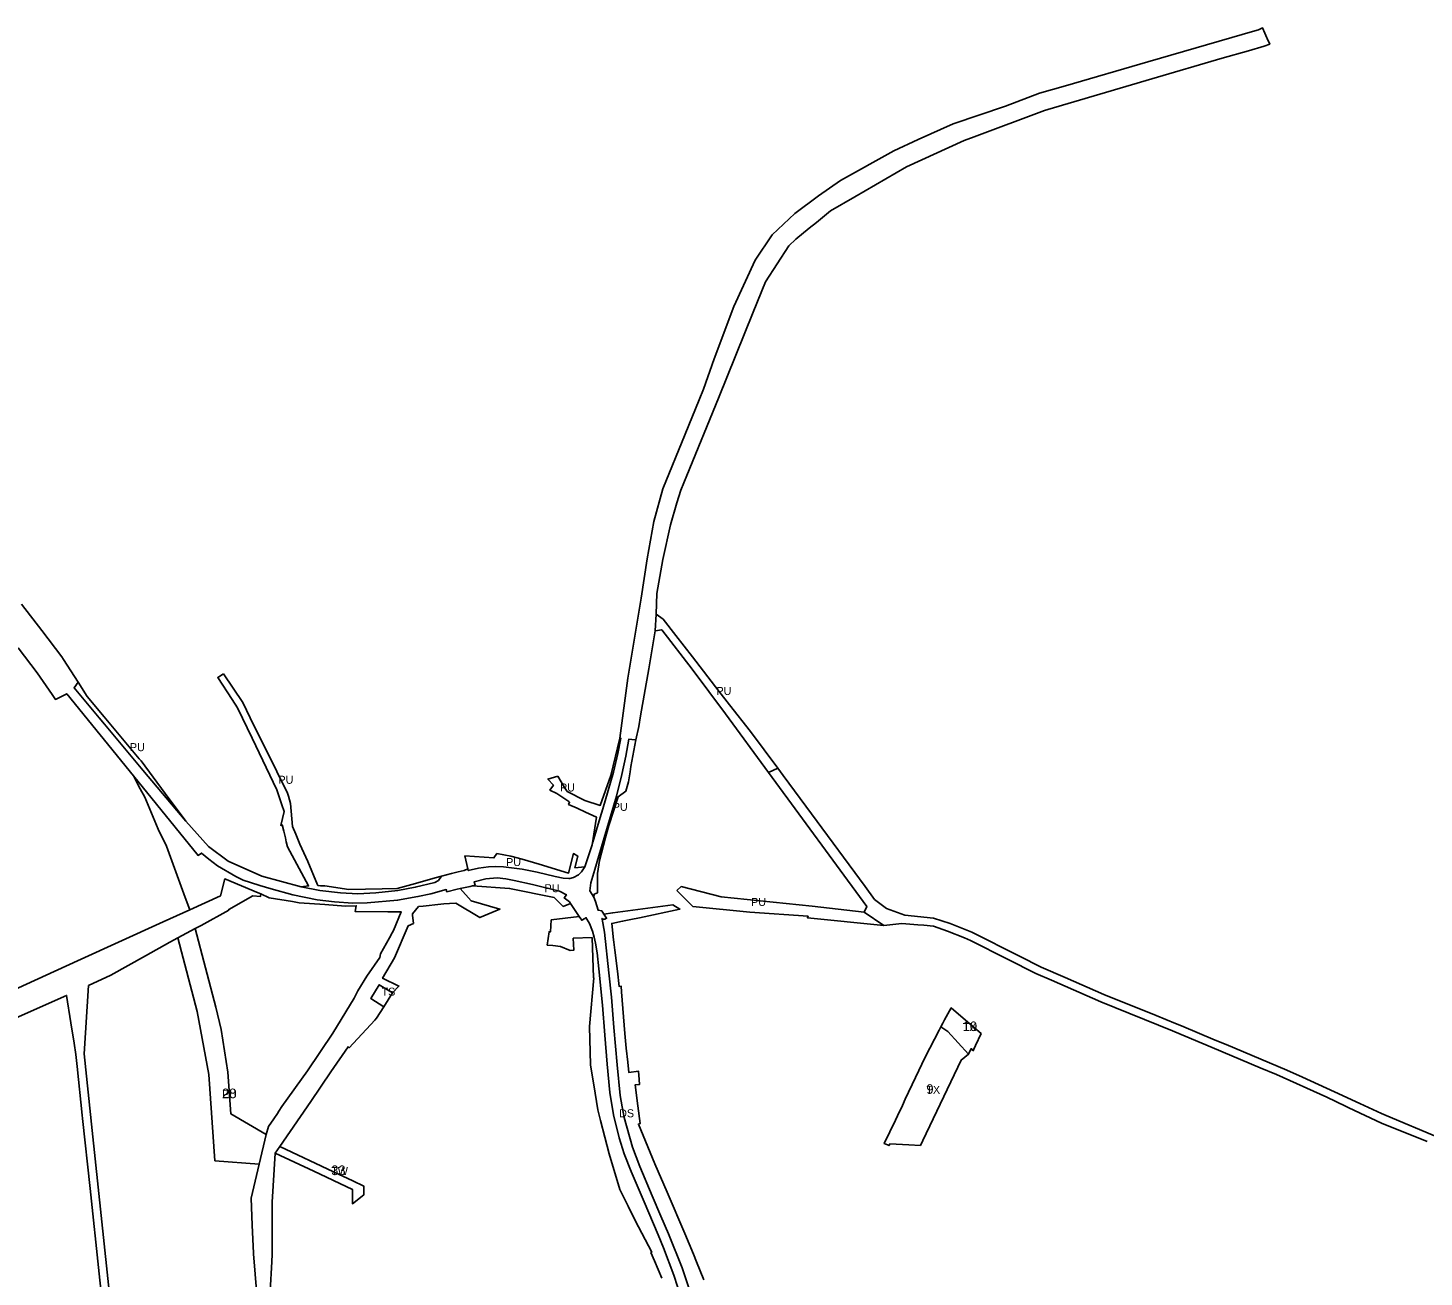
# Model space of a CAD drawing. Extents: x -521882 to -518995, y -1142400 to -1140153.
# Drawn here: x -520739 to -519867, y -1141035 to -1140255 of the extents above; entities that cross this region are included whole.
import ezdxf

# ---------------------------------------------------------------- set-up
doc = ezdxf.new("R2010")
doc.units = 0
for name, color, linetype in [('90320013', 7, 'Continuous'), ('90370013', 7, 'Continuous'), ('90390023', 7, 'Continuous'), ('90410013', 7, 'Continuous'), ('90440023', 7, 'Continuous'), ('90450013', 7, 'Continuous'), ('90450023', 7, 'Continuous'), ('ID_navrh', 7, 'Continuous')]:
    doc.layers.add(name, color=color, linetype=linetype)

msp = doc.modelspace()

# ---------------------------------------------------------------- linework, layer by layer
at = {"layer": '90320013'}
for points in [[(-520743.28, -1140615.01), (-520730.64, -1140631.58), (-520718.15, -1140647.9), (-520717.09, -1140649.55), (-520707.94, -1140663.79), (-520710.41, -1140667.24), (-520694.71, -1140686.16), (-520691.52, -1140689.98), (-520667.53, -1140718.71), (-520640.71, -1140750.61), (-520626.37, -1140766.52), (-520614.11, -1140775.58), (-520593.15, -1140785.04), (-520568.68, -1140791.66), (-520556.98, -1140793.85), (-520544.08, -1140795.45), (-520533.1, -1140795.95), (-520521.89, -1140795.42), (-520508.09, -1140793.94), (-520497.35, -1140791.93), (-520485.15, -1140788.87), (-520482.88, -1140787.7), (-520480.98, -1140785.01), (-520474.64, -1140783.36), (-520470.41, -1140782.37), (-520466.78, -1140781.53), (-520464.48, -1140780.47), (-520464.21, -1140781.48), (-520457.74, -1140780.06), (-520451.46, -1140779.1), (-520447.03, -1140778.94), (-520442.14, -1140779.17), (-520430.59, -1140780.58), (-520421.16, -1140782.56), (-520409.82, -1140785.14), (-520404.95, -1140786.22), (-520401.42, -1140786.48), (-520400.82, -1140786.35), (-520398.38, -1140785.83), (-520395.36, -1140784.1), (-520393.48, -1140782.23), (-520391.38, -1140779.15), (-520386.83, -1140765.41), (-520386.29, -1140763.79), (-520381.78, -1140748.3), (-520380.21, -1140742.93), (-520373.52, -1140720.12), (-520370.77, -1140708.37), (-520368.79, -1140698.83), (-520369.41, -1140698.76), (-520364.42, -1140661.36), (-520356.59, -1140613.91), (-520356.14, -1140611.39), (-520352.4, -1140586.73), (-520348.21, -1140563.43), (-520342.62, -1140543.01), (-520328.73, -1140508.82), (-520319.85, -1140487.51), (-520317.29, -1140480.75), (-520317.28, -1140480.73), (-520310.52, -1140461.93), (-520298.27, -1140429.16), (-520285.01, -1140400.23), (-520274.33, -1140384.38), (-520260.24, -1140370.94), (-520245.33, -1140359.99), (-520231.71, -1140350.36), (-520198.24, -1140332), (-520183.06, -1140324.86), (-520161.16, -1140315.09), (-520128.63, -1140303.97), (-520107.24, -1140295.95), (-520091.03, -1140291.29), (-520039.59, -1140276.29), (-519972.75, -1140256.9), (-519970.54, -1140256.24), (-519967.99, -1140255.12), (-519967.34, -1140256.59), (-519967.14, -1140257.04), (-519965.23, -1140261.32), (-519965.02, -1140261.78), (-519963.47, -1140265.25), (-519967, -1140266.42), (-519976.66, -1140269.42), (-519993.22, -1140274.03), (-520037.05, -1140286.83), (-520102.1, -1140306.15), (-520104.17, -1140306.68), (-520148.17, -1140323.1), (-520154.29, -1140325.48), (-520190.37, -1140341.83), (-520222.7, -1140360.61), (-520237.84, -1140369.42), (-520246.72, -1140376.59), (-520251.21, -1140380.2), (-520259.52, -1140387.05), (-520263.92, -1140391.15), (-520278.46, -1140413.78), (-520286.11, -1140432.61), (-520307.77, -1140486.46), (-520327.66, -1140534.75), (-520331.42, -1140543.88), (-520333.94, -1140551.84), (-520337.95, -1140565.45), (-520342.68, -1140587.14), (-520346.39, -1140608.35), (-520346.89, -1140621.24), (-520347.36, -1140631.75), (-520351.39, -1140655.57), (-520356.53, -1140684.75), (-520357.72, -1140691.49), (-520359.48, -1140699.91), (-520361.97, -1140699.61), (-520363.79, -1140699.4), (-520365.84, -1140710.09), (-520368.19, -1140721.56), (-520371.69, -1140734.94), (-520377.6, -1140755.34), (-520382.64, -1140772.35), (-520385.08, -1140780.78), (-520387.56, -1140789.2), (-520388.29, -1140794.2), (-520385.85, -1140798.14), (-520384.61, -1140800.83), (-520383.09, -1140806.25), (-520380.85, -1140806.63), (-520379.43, -1140808.81), (-520377.82, -1140811.29), (-520378.82, -1140811.8), (-520379.96, -1140811.88), (-520380.39, -1140811.76), (-520380.67, -1140811.43), (-520380.6, -1140811.79), (-520379.1, -1140819.91), (-520376.29, -1140845.28), (-520374.77, -1140860.47), (-520373.16, -1140879.42), (-520371.26, -1140902.9), (-520369.28, -1140921.92), (-520368.13, -1140929.14), (-520366.72, -1140935.8), (-520361.56, -1140954.25), (-520356.97, -1140966.32), (-520349.32, -1140984.59), (-520343.82, -1140997.39), (-520339.2, -1141008.34), (-520330.66, -1141029.65), (-520324.76, -1141047.17)], [(-520328.86, -1141055.37), (-520335.75, -1141034.28), (-520342.18, -1141017.11), (-520345.5, -1141009.13), (-520354.36, -1140988.48), (-520362.35, -1140969.44), (-520366.71, -1140958.45), (-520369.93, -1140948.53), (-520373.47, -1140934.03), (-520375.75, -1140920.12), (-520377.36, -1140902.45), (-520378.78, -1140884.3), (-520380.29, -1140865.65), (-520382.69, -1140842.89), (-520383.72, -1140832.94), (-520384.67, -1140826.92), (-520385.53, -1140823.04), (-520386.51, -1140819.33), (-520388.5, -1140814.63), (-520390.7, -1140810.83), (-520391.45, -1140811.33), (-520393.28, -1140812.54), (-520394.93, -1140810.08), (-520400.31, -1140802.09), (-520401.05, -1140800.99), (-520404.19, -1140798.55), (-520402.86, -1140796.64), (-520407.29, -1140794.34), (-520424.08, -1140790.09), (-520435.45, -1140787.73), (-520440.68, -1140786.74), (-520446.22, -1140786.13), (-520453.31, -1140786.74), (-520460.51, -1140788.53), (-520459.9, -1140790.65), (-520461.64, -1140791.05), (-520463.08, -1140791.37), (-520469.2, -1140792.72), (-520471.14, -1140793.15), (-520477.5, -1140794.69), (-520477.93, -1140793.38), (-520487.57, -1140796.09), (-520495.6, -1140797.79), (-520508.3, -1140799.99), (-520527.36, -1140801.68), (-520536.39, -1140801.86), (-520547.7, -1140801.1), (-520558.67, -1140799.71), (-520573.73, -1140796.75), (-520587.36, -1140792.97), (-520594.41, -1140790.88), (-520595.11, -1140790.67), (-520604.74, -1140787.54), (-520609.47, -1140785.27), (-520620.79, -1140778.52), (-520626.26, -1140774.29), (-520630.76, -1140770.61), (-520632.98, -1140772.07), (-520673.31, -1140722.41), (-520715.02, -1140671.04), (-520722.11, -1140674.56), (-520724.12, -1140671.61), (-520733.42, -1140657.97), (-520745.42, -1140642.26)]]:
    msp.add_lwpolyline(points, dxfattribs=at)
at = {"layer": '90370013'}
for points in [[(-519865.12, -1140950.76), (-519893.61, -1140939.25), (-519914.16, -1140929.63), (-519916.21, -1140928.63), (-519927.83, -1140922.94), (-519959.29, -1140908.89), (-519969.45, -1140904.62), (-519999.48, -1140892), (-520022.73, -1140882.19), (-520024.21, -1140881.57), (-520069.02, -1140863.47), (-520099.84, -1140850.03), (-520109.6, -1140845.72), (-520127.38, -1140836.75), (-520150.53, -1140825.07), (-520154.23, -1140823.56), (-520164.79, -1140819.27), (-520173.51, -1140816.17), (-520179.62, -1140815.67), (-520183.32, -1140815.4), (-520193.39, -1140814.61), (-520204.62, -1140815.75), (-520216.9, -1140807.42), (-520215.27, -1140803.99), (-520276.72, -1140720.19), (-520270.86, -1140717.61), (-520267.51, -1140722.14), (-520249.86, -1140745.99), (-520216.26, -1140791.5), (-520210.31, -1140799.64), (-520202.97, -1140805.12), (-520191.48, -1140809.25), (-520173.51, -1140811.18), (-520163.23, -1140814.61), (-520149.6, -1140820.02), (-520119.77, -1140834.99), (-520106.23, -1140841.79), (-520091.34, -1140848.28), (-520067.09, -1140858.86), (-520034.41, -1140872.06), (-520022.3, -1140876.95), (-520018.57, -1140878.52), (-519997.49, -1140887.4), (-519990.79, -1140890.22), (-519952.82, -1140906.1), (-519943.08, -1140910.55), (-519923.13, -1140919.66), (-519907.29, -1140926.89), (-519893.61, -1140933.19), (-519890.83, -1140934.46), (-519858.03, -1140948.23)], [(-520882.47, -1140917.37), (-520708.35, -1140837.86), (-520654.73, -1140813.47), (-520638.22, -1140805.93), (-520618.93, -1140797.21), (-520616.33, -1140786.69), (-520595.39, -1140795.43), (-520593.85, -1140796.07), (-520594.09, -1140797.76), (-520598.71, -1140797.27), (-520613.82, -1140805.77), (-520613.67, -1140806.13), (-520631.12, -1140815.76), (-520634.79, -1140817.77), (-520645.66, -1140823.61), (-520650.7, -1140826.31), (-520665.74, -1140834.79), (-520687.49, -1140846.81), (-520701.37, -1140853.35), (-520704.17, -1140895.93), (-520699.09, -1140943.92), (-520679.92, -1141124.76)], [(-520684.73, -1141127.15), (-520694.75, -1141033.39), (-520700.46, -1140980.02), (-520705.13, -1140936.35), (-520705.35, -1140934.26), (-520708.6, -1140903.84), (-520709.39, -1140896.44), (-520710.48, -1140889.38), (-520712.47, -1140876.54), (-520715.12, -1140859.45), (-520881.74, -1140933.43)]]:
    msp.add_lwpolyline(points, dxfattribs=at)
at = {"layer": '90390023'}
msp.add_lwpolyline([(-520581.88, -1140953.8), (-520548.43, -1140969.6), (-520536.34, -1140975.31), (-520529.45, -1140978.56), (-520529.52, -1140984.06), (-520536.52, -1140989.65), (-520536.41, -1140980.8), (-520560.76, -1140969.3), (-520584.75, -1140957.97)], close=True, dxfattribs=at)
at = {"layer": '90410013'}
msp.add_lwpolyline([(-520511.48, -1140857.9), (-520516.84, -1140866.53), (-520525.13, -1140861.38), (-520519.8, -1140852.78)], close=True, dxfattribs=at)
at = {"layer": '90440023'}
for points in [[(-520168.95, -1140879.03), (-520167.79, -1140876.9), (-520166.62, -1140874.78), (-520162.5, -1140867.24), (-520152.09, -1140876.15), (-520143.83, -1140883.35), (-520147.23, -1140890.72), (-520148.27, -1140892.97), (-520148.74, -1140894), (-520149.94, -1140892.73), (-520151.68, -1140896.26), (-520164.55, -1140881.96)], [(-520168.95, -1140879.03), (-520164.55, -1140881.96), (-520151.68, -1140896.26), (-520156.19, -1140899.86), (-520180.26, -1140950.09), (-520181.77, -1140953.24), (-520189.01, -1140952.86), (-520200.79, -1140952.24), (-520201.27, -1140953.32), (-520201.3, -1140953.32), (-520204.29, -1140951.99), (-520197.39, -1140937.44), (-520196.08, -1140934.67), (-520193, -1140928.16), (-520191.17, -1140924.29), (-520184.7, -1140910.65), (-520178.74, -1140898.05), (-520170.08, -1140881.1)]]:
    msp.add_lwpolyline(points, close=True, dxfattribs=at)
at = {"layer": '90450013'}
for points in [[(-520346.89, -1140621.24), (-520342.44, -1140624.55), (-520334.5, -1140634.63), (-520324.2, -1140648.06), (-520307.57, -1140669.43), (-520300.9, -1140678.05), (-520287.89, -1140694.59), (-520270.86, -1140717.61), (-520276.72, -1140720.19), (-520303.56, -1140683.6), (-520324.4, -1140655.71), (-520343.28, -1140631.04), (-520347.36, -1140631.75)], [(-520617.05, -1140658.61), (-520605.12, -1140676.44), (-520598.21, -1140690.89), (-520586.97, -1140713.22), (-520580.64, -1140725.97), (-520577.29, -1140732.42), (-520576.44, -1140734.91), (-520575.25, -1140739.5), (-520574.04, -1140754.01), (-520571.93, -1140758.73), (-520569.37, -1140764.94), (-520564.34, -1140775.92), (-520558.32, -1140790.33), (-520558.14, -1140790.76), (-520556.47, -1140791.09), (-520553.78, -1140791.02), (-520538.73, -1140793.3), (-520517.96, -1140792.82), (-520508.59, -1140792.61), (-520497.16, -1140789.47), (-520484.92, -1140786.1), (-520480.98, -1140785.01), (-520482.88, -1140787.7), (-520485.15, -1140788.87), (-520497.35, -1140791.93), (-520508.09, -1140793.94), (-520521.89, -1140795.42), (-520533.1, -1140795.95), (-520544.08, -1140795.45), (-520556.98, -1140793.85), (-520568.68, -1140791.66), (-520563.9, -1140791.05), (-520577.16, -1140766.7), (-520577.96, -1140763.57), (-520578.47, -1140761.14), (-520579.46, -1140756.88), (-520580.35, -1140753), (-520581.36, -1140753.24), (-520579.16, -1140744.51), (-520580.56, -1140740.45), (-520583.71, -1140731.03), (-520599.29, -1140698.77), (-520608.35, -1140679.79), (-520611.7, -1140674.57), (-520620.66, -1140660.83)], [(-520691.74, -1140685.4), (-520669.79, -1140711.59), (-520668.57, -1140712.91), (-520653.49, -1140733.31), (-520640.71, -1140750.61), (-520667.53, -1140718.71), (-520691.52, -1140689.98), (-520694.71, -1140686.16), (-520710.41, -1140667.24), (-520707.94, -1140663.79), (-520702.26, -1140672.84)], [(-520408.23, -1140722.45), (-520404.15, -1140729.51), (-520402.49, -1140732.06), (-520391.43, -1140737.8), (-520381.74, -1140740.77), (-520375.15, -1140722.06), (-520369.41, -1140698.76), (-520368.79, -1140698.83), (-520370.77, -1140708.37), (-520373.52, -1140720.12), (-520380.21, -1140742.93), (-520381.78, -1140748.3), (-520386.29, -1140763.79), (-520386.83, -1140765.41), (-520384.05, -1140748.14), (-520390.88, -1140745.01), (-520396.18, -1140742.58), (-520401.52, -1140740.13), (-520400.87, -1140738.78), (-520401.38, -1140738.43), (-520408.83, -1140733.26), (-520413.15, -1140731.24), (-520410.99, -1140728.16), (-520414.39, -1140724.32)], [(-520385.85, -1140798.14), (-520388.29, -1140794.2), (-520387.56, -1140789.2), (-520385.08, -1140780.78), (-520382.64, -1140772.35), (-520377.6, -1140755.34), (-520371.69, -1140734.94), (-520368.19, -1140721.56), (-520365.84, -1140710.09), (-520363.79, -1140699.4), (-520361.97, -1140699.61), (-520359.48, -1140699.91), (-520362.54, -1140716.5), (-520363.02, -1140719.82), (-520364.02, -1140726.04), (-520365.68, -1140731.9), (-520370.5, -1140735.37), (-520376.29, -1140753.27), (-520378.38, -1140760.91), (-520382.29, -1140775.26), (-520383.46, -1140783.32), (-520383.53, -1140795.4), (-520385.62, -1140796.31)], [(-520466.39, -1140772.32), (-520448.2, -1140773.61), (-520446.34, -1140770.88), (-520437.68, -1140772.4), (-520430.49, -1140774.45), (-520419.92, -1140777.53), (-520401.54, -1140783.02), (-520398.45, -1140770.83), (-520395.82, -1140772.4), (-520397.56, -1140779.72), (-520391.38, -1140779.15), (-520393.48, -1140782.23), (-520395.36, -1140784.1), (-520398.38, -1140785.83), (-520400.82, -1140786.35), (-520401.42, -1140786.48), (-520404.95, -1140786.22), (-520409.82, -1140785.14), (-520421.16, -1140782.56), (-520430.59, -1140780.58), (-520442.14, -1140779.17), (-520447.03, -1140778.94), (-520451.46, -1140779.1), (-520457.74, -1140780.06), (-520464.21, -1140781.48), (-520464.48, -1140780.47)], [(-520400.31, -1140802.09), (-520404.93, -1140803.86), (-520410.6, -1140798.4), (-520438.34, -1140792.64), (-520461.64, -1140791.05), (-520459.9, -1140790.65), (-520460.51, -1140788.53), (-520453.31, -1140786.74), (-520446.22, -1140786.13), (-520440.68, -1140786.74), (-520435.45, -1140787.73), (-520424.08, -1140790.09), (-520407.29, -1140794.34), (-520402.86, -1140796.64), (-520404.19, -1140798.55), (-520401.05, -1140800.99)], [(-520333.88, -1140793.93), (-520331.09, -1140791.46), (-520306.3, -1140797.86), (-520249.32, -1140803.75), (-520216.9, -1140807.42), (-520204.62, -1140815.75), (-520252.34, -1140811), (-520251.92, -1140810), (-520288.38, -1140807.41), (-520323.97, -1140803.87)]]:
    msp.add_lwpolyline(points, close=True, dxfattribs=at)
for points in [[(-520596.21, -1141046.3), (-520598.37, -1141020.83), (-520598.4, -1141020.44), (-520599.09, -1141003), (-520599.73, -1140986.18), (-520594.75, -1140964.79), (-520590.36, -1140946.34), (-520588.9, -1140941.38), (-520585.74, -1140936.61), (-520583.47, -1140933.16), (-520582.55, -1140931.77), (-520580.62, -1140928.87), (-520564.56, -1140906.56), (-520548.74, -1140883.02), (-520535.38, -1140861.16), (-520533.13, -1140856.68), (-520527.5, -1140847.46), (-520519.49, -1140835.7), (-520518.98, -1140833.57), (-520513.38, -1140823.43), (-520511.64, -1140820.3), (-520510.91, -1140818.98), (-520506.04, -1140807.36), (-520514.4, -1140807.37), (-520534.78, -1140807.16), (-520534.2, -1140803.46), (-520540.96, -1140803.77), (-520553.77, -1140802.66), (-520569.82, -1140801.63), (-520573.94, -1140800.9), (-520588.57, -1140798.45), (-520593.85, -1140796.07), (-520595.39, -1140795.43), (-520616.33, -1140786.69), (-520618.93, -1140797.21), (-520638.22, -1140805.93), (-520641.11, -1140798.37), (-520652.69, -1140766.32), (-520657.82, -1140755.57), (-520666.3, -1140735.71), (-520669.12, -1140730.36), (-520673.31, -1140722.41), (-520632.98, -1140772.07), (-520630.76, -1140770.61), (-520626.26, -1140774.29), (-520620.79, -1140778.52), (-520609.47, -1140785.27), (-520604.74, -1140787.54), (-520595.11, -1140790.67), (-520594.41, -1140790.88), (-520587.36, -1140792.97), (-520573.73, -1140796.75), (-520558.67, -1140799.71), (-520547.7, -1140801.1), (-520536.39, -1140801.86), (-520527.36, -1140801.68), (-520508.3, -1140799.99), (-520495.6, -1140797.79), (-520487.57, -1140796.09), (-520477.93, -1140793.38), (-520477.5, -1140794.69), (-520471.14, -1140793.15), (-520469.2, -1140792.72), (-520462.48, -1140800.42), (-520444.45, -1140805.57), (-520456.93, -1140810.9), (-520471.87, -1140801.78), (-520475.9, -1140802.08), (-520479.52, -1140802.35), (-520481.31, -1140802.54), (-520492.42, -1140803.71), (-520495.25, -1140804.01), (-520499.12, -1140808.43), (-520499.02, -1140809.41), (-520498.5, -1140814.52), (-520501.75, -1140815.97), (-520510.31, -1140835.9), (-520517.77, -1140848.71), (-520507.49, -1140853.67), (-520511.48, -1140857.9), (-520519.8, -1140852.78), (-520525.13, -1140861.38), (-520516.84, -1140866.53), (-520521.46, -1140873.68), (-520522.62, -1140874.92), (-520538.57, -1140892.18), (-520539.31, -1140891.51), (-520549.95, -1140907.16), (-520562.58, -1140925.73), (-520581.88, -1140953.8), (-520584.75, -1140957.97), (-520586.68, -1140988.64), (-520586.76, -1141021.16), (-520586.99, -1141025.98), (-520587.85, -1141044.25)], [(-520343.25, -1141036.1), (-520347.88, -1141025.34), (-520350.1, -1141020.17), (-520349.61, -1141019.9), (-520359.98, -1141000.07), (-520364.35, -1140991.14), (-520369.44, -1140980.74), (-520376.07, -1140958.44), (-520381.51, -1140937.64), (-520383.27, -1140930.85), (-520385, -1140920.46), (-520387.91, -1140902.86), (-520388.38, -1140878.81), (-520385.81, -1140848.46), (-520386.02, -1140848.4), (-520386.88, -1140823.39), (-520398.57, -1140823.79), (-520398.31, -1140831.29), (-520400.46, -1140831.36), (-520406.52, -1140828.82), (-520411.4, -1140828.34), (-520414.81, -1140828.01), (-520413.68, -1140819.71), (-520412.85, -1140819.83), (-520412.34, -1140812.28), (-520394.93, -1140810.08), (-520393.28, -1140812.54), (-520391.45, -1140811.33), (-520390.7, -1140810.83), (-520388.5, -1140814.63), (-520386.51, -1140819.33), (-520385.53, -1140823.04), (-520384.67, -1140826.92), (-520383.72, -1140832.94), (-520382.69, -1140842.89), (-520380.29, -1140865.65), (-520378.78, -1140884.3), (-520377.36, -1140902.45), (-520375.75, -1140920.12), (-520373.47, -1140934.03), (-520369.93, -1140948.53), (-520366.71, -1140958.45), (-520362.35, -1140969.44), (-520354.36, -1140988.48), (-520345.5, -1141009.13), (-520342.18, -1141017.11), (-520335.75, -1141034.28), (-520328.86, -1141055.37)], [(-520324.76, -1141047.17), (-520330.66, -1141029.65), (-520339.2, -1141008.34), (-520343.82, -1140997.39), (-520349.32, -1140984.59), (-520356.97, -1140966.32), (-520361.56, -1140954.25), (-520366.72, -1140935.8), (-520368.13, -1140929.14), (-520369.28, -1140921.92), (-520371.26, -1140902.9), (-520373.16, -1140879.42), (-520374.77, -1140860.47), (-520376.29, -1140845.28), (-520379.1, -1140819.91), (-520380.6, -1140811.79), (-520380.67, -1140811.43), (-520380.39, -1140811.76), (-520379.96, -1140811.88), (-520378.82, -1140811.8), (-520377.82, -1140811.29), (-520379.43, -1140808.81), (-520373.88, -1140807.82), (-520336.41, -1140802.99), (-520331.98, -1140805.6), (-520332, -1140805.6), (-520357.19, -1140810.98), (-520362.72, -1140812.11), (-520367.81, -1140813.15), (-520374.57, -1140814.53), (-520373.37, -1140824.7), (-520373.19, -1140826.31), (-520372.63, -1140831.2), (-520371.04, -1140844.39), (-520369.93, -1140853.84), (-520368.63, -1140853.74), (-520368.38, -1140857.16), (-520366.29, -1140883.26), (-520365.47, -1140892.49), (-520364.55, -1140901.11), (-520363.85, -1140907.67), (-520357.79, -1140906.87), (-520357.38, -1140911.92), (-520357.13, -1140915.06), (-520359.88, -1140915.32), (-520358.24, -1140928.5), (-520356.86, -1140939.57), (-520357.85, -1140939.9), (-520347.56, -1140964.58), (-520339.88, -1140982.4), (-520328.8, -1141008.12), (-520323.52, -1141021.14), (-520321.6, -1141025.87), (-520317.01, -1141037.16)]]:
    msp.add_lwpolyline(points, dxfattribs=at)
at = {"layer": '90450023'}
msp.add_lwpolyline([(-520634.79, -1140817.77), (-520621.9, -1140866.86), (-520618.56, -1140880.81), (-520614.37, -1140907.34), (-520612.5, -1140933.48), (-520590.36, -1140946.34), (-520594.75, -1140964.79), (-520622.44, -1140962.75), (-520626.29, -1140908.87), (-520633.62, -1140869.48), (-520645.66, -1140823.61)], close=True, dxfattribs=at)

# ---------------------------------------------------------------- texts
at = {"layer": '90320013'}
msp.add_text('DS', height=5, rotation=360, dxfattribs=at).set_placement((-520369.92, -1140935.6))
at = {"layer": '90390023'}
msp.add_text('TW', height=5, rotation=360, dxfattribs=at).set_placement((-520549.78, -1140971.72))
at = {"layer": '90410013'}
msp.add_text('TS', height=5, rotation=0, dxfattribs=at).set_placement((-520518.3, -1140859.66))
at = {"layer": '90440023'}
for p in [(-520155.27, -1140881.75), (-520177.99, -1140920.96)]:
    msp.add_text('TX', height=5, rotation=360, dxfattribs=at).set_placement(p)
at = {"layer": '90450013'}
for rotation, p in [(360, (-520309.11, -1140671.81)), (360, (-520675.56, -1140706.9)), (0, (-520582.74, -1140727.28)), (360, (-520406.89, -1140732.08)), (360, (-520373.89, -1140744.18)), (360, (-520440.53, -1140778.66)), (0, (-520416.51, -1140795)), (360, (-520287.48, -1140803.61))]:
    msp.add_text('PU', height=5, rotation=rotation, dxfattribs=at).set_placement(p)
at = {"layer": '90450023'}
msp.add_text('PU', height=5, rotation=0, dxfattribs=at).set_placement((-520618.01, -1140923.68))
at = {"layer": 'ID_navrh'}
for s, rotation, p in [('10', 0, (-520155.27, -1140881.75)), ('9', 0, (-520177.99, -1140920.96)), ('33', 360, (-520549.78, -1140971.72))]:
    msp.add_text(s, height=6, rotation=rotation, dxfattribs=at).set_placement(p)
msp.add_text('28', height=6, dxfattribs=at).set_placement((-520618.01, -1140923.68))

doc.saveas('drawing.dxf')
